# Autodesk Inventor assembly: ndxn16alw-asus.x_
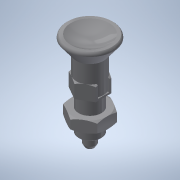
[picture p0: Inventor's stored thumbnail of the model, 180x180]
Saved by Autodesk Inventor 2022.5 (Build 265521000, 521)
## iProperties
Part Number: ndxn16alw-asus.x_
Material: 一般
Document SubType Name: Assembly
Designer: ImaoCorp
Sending System: SOLIDWORKS 2017-2017317
MC: AMD64
MC_MODEL: Intel64 Family 6 Model 60 Stepping 3, GenuineIntel
OS: Windows_NT
FRU: Parasolid Version 29.0, build 201,  4-17-2017
FORMAT: text
GUISE: transmit
KEY: ndxn16alw-asus
FILE: ndxn16alw-asus.x_t
DATE: Wed Sep 04 15:28:42 2019
Author: ImaoCorp
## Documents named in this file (3)
- X:\14_SW2022-Inv2022\00_全2023-1023新製品(TCC)まで\n\ndxn16alw-asus\NDXN16ALW-ASUS.iam
- X:\14_SW2022-Inv2022\00_全2023-1023新製品(TCC)まで\n\ndxn16alw-asus\ndxn16alw-asus_01.ipt
- X:\14_SW2022-Inv2022\00_全2023-1023新製品(TCC)まで\n\ndxn16alw-asus\ndxn16alw-asus_02.ipt
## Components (2 placed, 2 different names)
1. ndxn16alw-asus_01
2. ndxn16alw-asus_02
